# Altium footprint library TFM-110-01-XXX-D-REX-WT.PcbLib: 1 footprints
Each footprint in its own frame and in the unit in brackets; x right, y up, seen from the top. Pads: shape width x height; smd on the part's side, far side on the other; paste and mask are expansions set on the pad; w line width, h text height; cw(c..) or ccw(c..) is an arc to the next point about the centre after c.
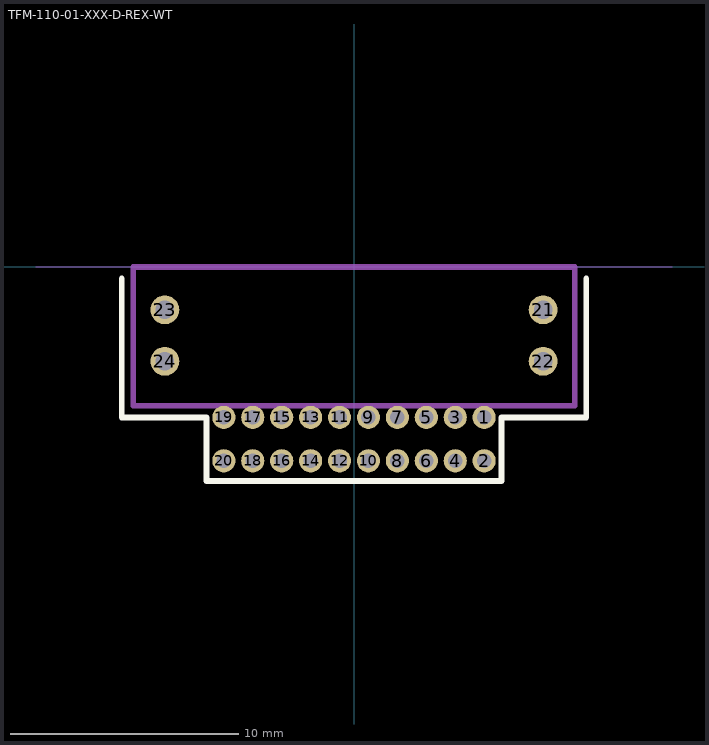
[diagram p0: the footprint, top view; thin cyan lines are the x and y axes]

## TFM-110-01-XXX-D-REX-WT [mil]
pads (24):
  round 40 hole 25 mask+3: 1(225,-260) 2(225,-335) 3(175,-260) 4(175,-335) 5(125,-260) 6(125,-335) 7(75,-260) 8(75,-335) 9(25,-260) 10(25,-335) 11(-25,-260) 12(-25,-335) 13(-75,-260) 14(-75,-335) 15(-125,-260) 16(-125,-335) 17(-175,-260) 18(-175,-335) 19(-225,-260) 20(-225,-335)
  round 50 hole 32 mask+3: 21(327,-74) 22(327,-163) 23(-327,-74) 24(-327,-163)
Top Overlay:
  lines w10: -401.5,-20 -401.5,-260 -255,-260 -255,-370 255,-370 255,-260 401.5,-260 401.5,-20
Mechanical 1:
  lines w10: -381.5,-240 -381.5,0 381.5,0 381.5,-240 -381.5,-240
  text "J1" at -17.57,-164.07 h30
Mechanical 16:
  lines w1: -550,0 550,0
